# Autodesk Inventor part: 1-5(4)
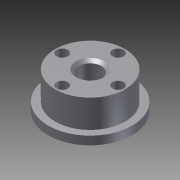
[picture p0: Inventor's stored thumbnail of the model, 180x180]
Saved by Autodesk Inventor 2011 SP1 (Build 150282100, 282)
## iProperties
Created: 2014-02
Part Number: 1-5(4)
Document SubType Name: Modeling
Designer: Administrator
Density: 1 g/cm^3
Author: Administrator
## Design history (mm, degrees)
sketch "草图1"
  geometry: C1 r 15 at (0, 0); 1 further point
  constraints: 1 centre point, 1 coincident
  dimensions: "d0" = 30 diameter of C1
extrude "拉伸1" new body sketch "草图1" distance "d1" = 3; taper "d2" = 0 deg
sketch "草图2"
  geometry: C1 r 15 at (0, 0) reference; C2 r 12.5 at (0, 0)
  constraints: 1 centre point, 1 coincident
  dimensions: "d3" = 25 diameter of C2
extrude "拉伸2" join sketch "草图2" distance "d4" = 10; taper "d5" = 0 deg
sketch "草图3"
  geometry: C1 r 12.5 at (0, 0) reference; C2 r 4 at (0, 0)
  constraints: 1 centre point, 1 coincident
  dimensions: "d6" = 8 diameter of C2
extrude "拉伸3" cut sketch "草图3" stored distance "d7" = 10; taper "d8" = 0 deg
chamfer "倒角1" distance "d9" = 1; stored, may be unused: second distance "d10" = 2, angle "d11" = 45 deg
chamfer "倒角2" distance "d12" = 1; stored, may be unused: second distance "d13" = 2, angle "d14" = 45 deg
sketch "草图4"
  geometry: C1 r 5 at (0, 0) reference; C2 r 1 at (0, 10); C3 r 1 at (0, -10); C4 r 1 at (10, 0); C5 r 1 at (-10, 0); A1 r 10 centre (0, 0) between (0, 10) and (0, -10)
  constraints: 5 centre point, 4 point on circle, 1 coincident
  dimensions: "d15" = 20 diameter of A1; "d16" = 2 diameter of C2; "d17" = 2 diameter of C3; "d18" = 2 diameter of C4; "d19" = 2 diameter of C5
extrude "拉伸4" cut sketch "草图4" stored distance "d20" = 10; taper "d21" = 0 deg
hole "Hole1" diameter "d24" = 4; stored, may be unused: countersink angle "d28" = 90 deg, drill point angle "d30" = 118 deg; dims "d22" = 10, "d23" = 10, "d25" = 6, "d26" = 4, "d27" = 2, "d29" = 5
pattern_circular "环形阵列1" dims angle "d32" = 360 deg
hole "Hole2" diameter "d36" = 4; stored, may be unused: countersink angle "d40" = 90 deg, drill point angle "d42" = 118 deg; dims "d34" = 10, "d35" = 10, "d37" = 6, "d38" = 4, "d39" = 2, "d41" = 5
pattern_circular "环形阵列2" dims angle "d44" = 360 deg
node "实体1"
